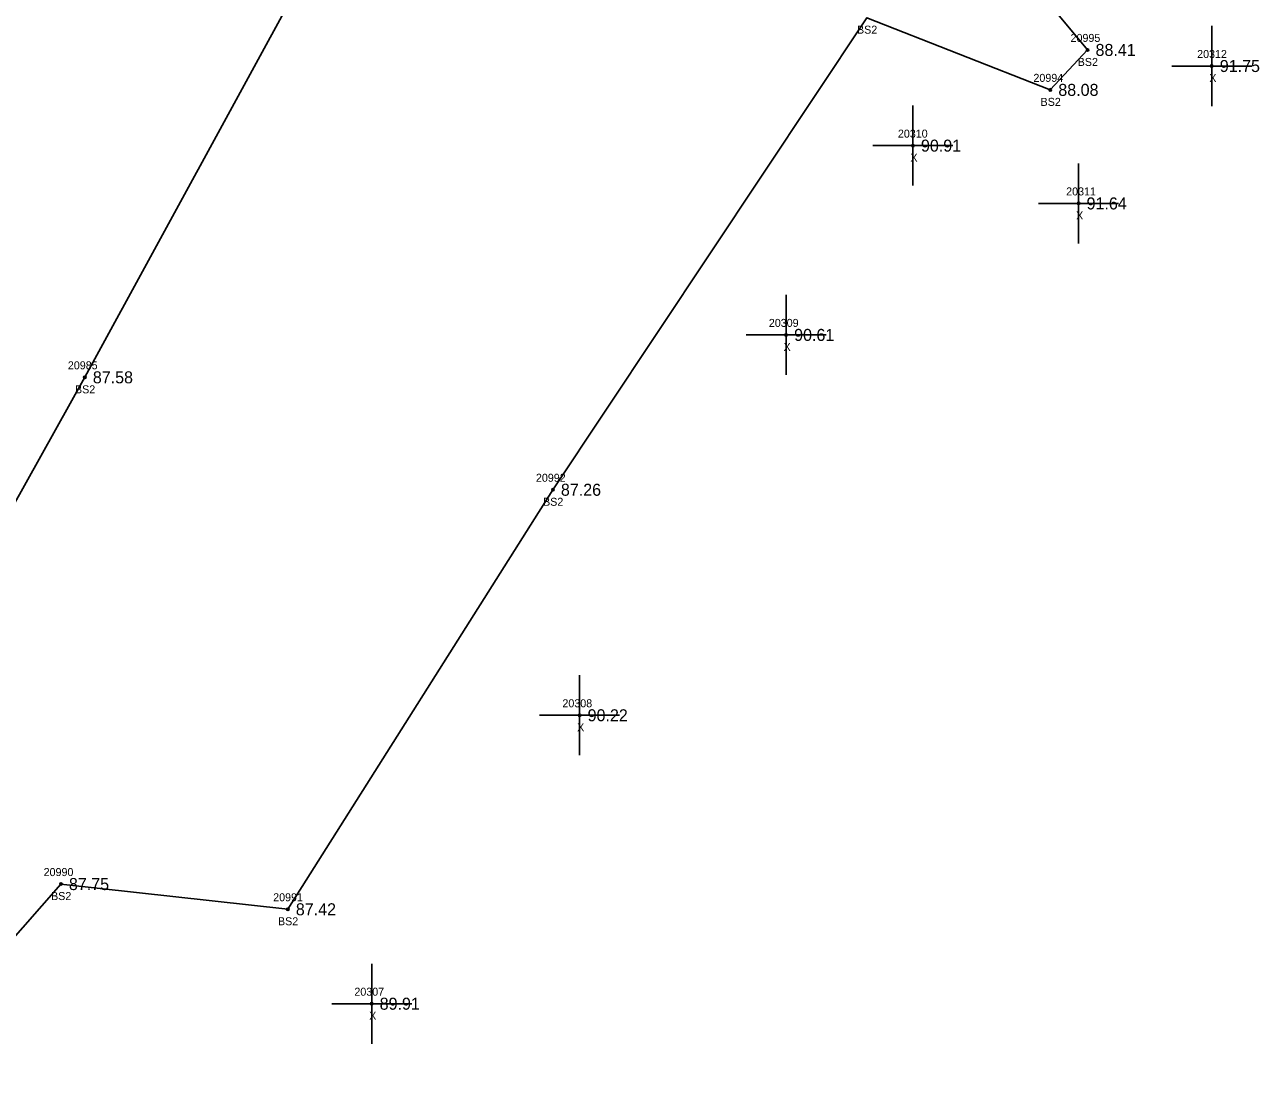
# Model space of a CAD drawing. Extents: x 2530197 to 2532051, y 935230 to 936631.
# Drawn here: x 2531837.5 to 2531991.8, y 936328 to 936460.9 of the extents above; entities that cross this region are included whole.
import ezdxf

# ---------------------------------------------------------------- set-up
doc = ezdxf.new("R2010")
doc.units = 0
for name, color, linetype in [('RD_DTM_BkLn2', 7, 'Continuous'), ('RD_DTM_BkLn_txCode', 7, 'Continuous'), ('RD_EX_Misc', 7, 'Continuous'), ('RD_EX_Misc_txCode', 7, 'Continuous'), ('RD_EX_TX_Misc_ELEV', 7, 'Continuous'), ('RD_SMD_Locator', 7, 'Continuous')]:
    doc.layers.add(name, color=color, linetype=linetype)

msp = doc.modelspace()

# ---------------------------------------------------------------- linework, layer by layer
at = {"layer": 'RD_DTM_BkLn2'}
msp.add_lwpolyline([(2531917.54, 936550.96), (2531882.37, 936485.34), (2531845.03, 936416.88), (2531807.92, 936350.36), (2531800.08, 936331.1), (2531815.28, 936323.11), (2531842.04, 936353.56), (2531870.4, 936350.41), (2531903.53, 936402.83), (2531942.77, 936461.82), (2531965.7, 936452.8), (2531970.35, 936457.79), (2531954.01, 936477.47), (2531964.77, 936498.69)], dxfattribs=at)
at = {"layer": 'RD_EX_Misc'}
for p, q in [((2531985.88, 936450.78), (2531985.88, 936460.78)), ((2531980.88, 936455.78), (2531990.88, 936455.78)), ((2531948.53, 936440.83), (2531948.53, 936450.83)), ((2531943.53, 936445.83), (2531953.53, 936445.83)), ((2531969.23, 936433.61), (2531969.23, 936443.61)), ((2531964.23, 936438.61), (2531974.23, 936438.61)), ((2531932.68, 936417.18), (2531932.68, 936427.18)), ((2531927.68, 936422.18), (2531937.68, 936422.18)), ((2531906.87, 936369.65), (2531906.87, 936379.65)), ((2531901.87, 936374.65), (2531911.87, 936374.65)), ((2531880.88, 936333.61), (2531880.88, 936343.61)), ((2531875.88, 936338.61), (2531885.88, 936338.61))]:
    msp.add_line(p, q, dxfattribs=at)
at = {"layer": 'RD_SMD_Locator'}
for centre in [(2531970.35, 936457.79), (2531985.88, 936455.78), (2531965.7, 936452.8), (2531948.53, 936445.83), (2531969.23, 936438.61), (2531932.68, 936422.18), (2531845.03, 936416.88), (2531903.53, 936402.83), (2531906.87, 936374.65), (2531842.04, 936353.56), (2531870.4, 936350.41), (2531880.88, 936338.61)]:
    msp.add_circle(centre, 0.15, dxfattribs=at)

# ---------------------------------------------------------------- texts
at = {"layer": 'RD_DTM_BkLn_txCode'}
for s, p in [('BS2', (2531941.54, 936459.82)), ('20995', (2531968.23, 936458.79)), ('BS2', (2531969.12, 936455.79)), ('20994', (2531963.59, 936453.8)), ('BS2', (2531964.48, 936450.8)), ('20985', (2531842.91, 936417.88)), ('BS2', (2531843.8, 936414.88)), ('20992', (2531901.41, 936403.83)), ('BS2', (2531902.3, 936400.83)), ('20990', (2531839.88, 936354.56)), ('BS2', (2531840.81, 936351.56)), ('20991', (2531868.57, 936351.41)), ('BS2', (2531869.17, 936348.41))]:
    msp.add_text(s, height=1, dxfattribs=at).set_placement(p)
at = {"layer": 'RD_EX_Misc_txCode'}
for s, p in [('20312', (2531984.05, 936456.78)), ('X', (2531985.57, 936453.78)), ('20310', (2531946.65, 936446.83)), ('X', (2531948.21, 936443.83)), ('20311', (2531967.68, 936439.61)), ('X', (2531968.92, 936436.61)), ('20309', (2531930.52, 936423.18)), ('X', (2531932.36, 936420.18)), ('20308', (2531904.72, 936375.65)), ('X', (2531906.56, 936372.65)), ('20307', (2531878.72, 936339.61)), ('X', (2531880.57, 936336.61))]:
    msp.add_text(s, height=1, dxfattribs=at).set_placement(p)
at = {"layer": 'RD_EX_TX_Misc_ELEV'}
for s, p in [('88.41', (2531971.35, 936457.04)), ('91.75', (2531986.88, 936455.03)), ('88.08', (2531966.7, 936452.05)), ('90.91', (2531949.53, 936445.08)), ('91.64', (2531970.23, 936437.86)), ('90.61', (2531933.68, 936421.43)), ('87.58', (2531846.03, 936416.13)), ('87.26', (2531904.53, 936402.08)), ('90.22', (2531907.87, 936373.9)), ('87.75', (2531843.04, 936352.81)), ('87.42', (2531871.4, 936349.66)), ('89.91', (2531881.88, 936337.86))]:
    msp.add_text(s, height=1.5, dxfattribs=at).set_placement(p)

doc.saveas('drawing.dxf')
